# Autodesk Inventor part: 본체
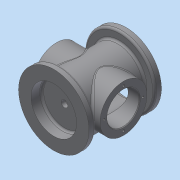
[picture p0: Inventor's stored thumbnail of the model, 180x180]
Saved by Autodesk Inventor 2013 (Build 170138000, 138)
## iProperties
Created: 2018-02
Part Number: 본체
Material: 일반
Document SubType Name: Modeling
Designer: dgall
Density: 1 g/cm^3
Author: dgall
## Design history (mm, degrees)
sketch "스케치1"
  geometry: L1 (0, 54)-(0, -54); L2 (-52.5, 54)-(-37, 54); L3 (-37, 54)-(-37, 47); L4 (-37, 47)-(-33, 47); L5 (-34, -38)-(-34, -54); L6 (-34, -54)-(-52.5, -54); L7 (-52.5, -54)-(-52.5, -44); L8 (-52.5, -44)-(-38, -44); L9 (-38, -44)-(-38, 44); L10 (-38, 44)-(-52.5, 44); L11 (-52.5, 44)-(-52.5, 54); L12 (-34, -38)-(-5, -38); L13 (-5, -38)-(-5, -32); L14 (-33, 47)-(-33, -32); L15 (-33, -32)-(-5, -32); 2 further points
  constraints: 30 end point, 8 parallel, 5 perpendicular, 2 coincident, 2 horizontal alignment, 1 midpoint, 1 vertical
  dimensions: "d0" = 108 distance of L1.start L1.end; "d2" = 105 diameter of L11 L1; "d3" = 74 diameter of L3 L1; "d5" = 68 diameter of L5 L1; "d6" = 105 diameter of L7 L1; "d7" = 76 diameter of L9 L1; "d8" = 10 distance of L6.end L7.end; "d9" = 10 distance of L10.end L2.start; "d10" = 7 distance of L2.end L3.end; "d11" = 16 distance of L5.start L5.end; "d27" = 10 diameter of L13 L1; "d28" = 79 distance of L4.end L14.end; "d29" = 66 diameter of L14 L1
revolve "회전1" sketch "스케치1" stored, may be unused: angle "d12" = 90 deg
node "작업 평면1"
sketch "스케치2"
  geometry: C1 r 35 at (0, 0); C2 r 24 at (0, 0); 1 further point
  constraints: 2 centre point, 2 coincident
  dimensions: "d14" = 70 diameter of C1; "d15" = 48 diameter of C2
extrude "돌출1" join sketch "스케치2" stored distance "d16" = 10; taper "d17" = 0 deg
extrude "돌출2" cut sketch "스케치2" stored distance "d18" = 10; taper "d19" = 0 deg
node "작업 평면3"
sketch "스케치3"
  geometry: L1 (-7, 13)-(-7, -13); L2 (7, 13)-(7, -13); A1 r 7 centre (0, 13) between (7, 13) and (-7, 13); A2 r 7 centre (0, -13) between (-7, -13) and (7, -13); 2 further points
  constraints: 4 end point, 4 point on circle, 2 centre point, 2 tangent, 2 vertical, 2 vertical alignment, 1 horizontal alignment, 1 midpoint
  dimensions: "d21" = 7 radius of A1; "d22" = 7 radius of A2; "d24" = 40 dimension on A1 A2
extrude "돌출3" join sketch "스케치3" stored distance "d25" = 10; taper "d26" = 15 deg
fillet "모깎기1" dims "d30" = 3
sketch "스케치4" dims "d31" = 58
  geometry: C1 r 24 at (0, 0) reference; C2 r 35 at (0, 0) reference; 2 further points
  constraints: 2 vertical alignment, 1 coincident, 2 other
hole "구멍1" sketch "스케치4" at (0, 29) diameter "d32" = 3.242; stored, may be unused: countersink angle "d36" = 90 deg, drill point angle "d38" = 118 deg; dims "d33" = 4, "d34" = 4, "d35" = 2, "d37" = 6
node "작업 평면4"
sketch "스케치5" dims "d42" = 90
  geometry: C1 r 52.5 at (0, 0) reference; 3 further points
  constraints: 2 coincident, 2 vertical alignment, 2 other
hole "구멍2" sketch "스케치5" at (0, 45), (0, 0) diameter "d43" = 3.242; stored, may be unused: countersink angle "d47" = 90 deg, drill point angle "d49" = 118 deg; dims "d44" = 4, "d45" = 4, "d46" = 2, "d48" = 6
chamfer "모따기1" distance "d53" = 1; stored, may be unused: second distance "d54" = 2, angle "d55" = 45 deg
chamfer "모따기2" distance "d56" = 1; stored, may be unused: second distance "d57" = 2, angle "d58" = 45 deg
sketch "스케치6"
  geometry: A1 r 7 centre (0, 13) between (7, 13) and (-7, 13) reference; A2 r 7 centre (0, -13) between (-7, -13) and (7, -13) reference; 3 further points
  constraints: 2 coincident
hole "구멍3" sketch "스케치6" at (0, 13), (0, -13) diameter "d59" = 4.134; stored, may be unused: countersink angle "d63" = 90 deg, drill point angle "d65" = 118 deg; dims "d60" = 6, "d61" = 4, "d62" = 2, "d64" = 8
fillet "모깎기2" dims "d66" = 3
sketch "스케치7"
  geometry: C1 r 49.5 at (0, 0) reference; C2 r 43 at (0, 0)
  constraints: 1 centre point, 1 coincident, 1 other
  dimensions: "d67" = 86 diameter of C2
feature "엠보싱1" sketch "스케치7" dims "d0" = 108, "d2" = 105, "d3" = 74, "d5" = 68, "d6" = 105, "d7" = 76, "d8" = 10, "d9" = 10, "d10" = 7, "d11" = 16, "d18" = 10, "d27" = 10, "d28" = 79, "d29" = 66, "d68" = 0.5, "d69" = 0
node "솔리드1"
mirror "대칭1"
pattern_circular "원형 패턴1" dims angle "d40" = 360 deg
mirror "대칭2"
pattern_circular "원형 패턴2" dims angle "d51" = 360 deg
node "작업 평면2"
other parameters: "d20" = -55
